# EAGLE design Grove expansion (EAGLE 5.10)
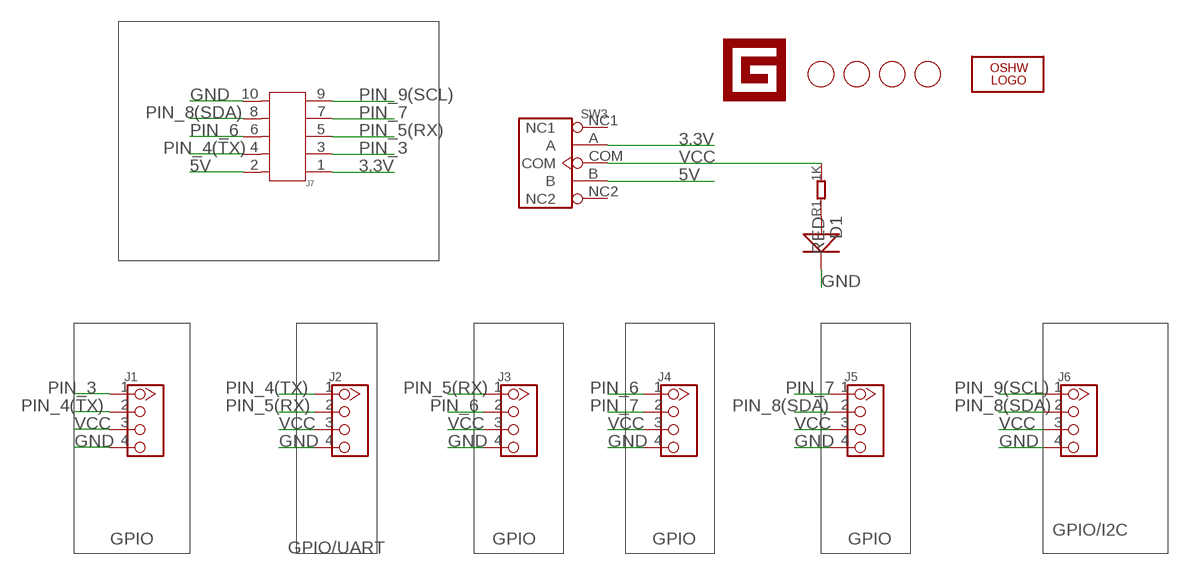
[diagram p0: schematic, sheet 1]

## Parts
D1  RED  D-0603  [SOD523]
J1  TWIG-4P-2.0-2.0  [4P-2.0]
J2  TWIG-4P-2.0-2.0  [4P-2.0]
J3  TWIG-4P-2.0-2.0  [4P-2.0]
J4  TWIG-4P-2.0-2.0  [4P-2.0]
J5  TWIG-4P-2.0-2.0  [4P-2.0]
J6  TWIG-4P-2.0-2.0  [4P-2.0]
J7  HEADER-SHF-105-01-L-D-SM  [SHF-105-01-L-D-SM]
LOGO2  LOGO-OSHW-FILLX0150-NT  [OSHW_FILLX150_NOTEXT]
R1  1K  R-0603  [0603]
SW3  SWITCH-2H-3P-REINFORCE  [3P-2CH-2.0-8.8X4.4X4.7H-90D-REINFORCE]
U$1  LOGO-GADGETEER-NORMAL  [GADGETEER-SILK]
U$2  PAD-HOLE'3.2/7.0'  [HOLE-D-3.2/7.0]
U$3  PAD-HOLE'3.2/7.0'  [HOLE-D-3.2/7.0]
U$4  PAD-HOLE'3.2/7.0'  [HOLE-D-3.2/7.0]
U$5  PAD-HOLE'3.2/7.0'  [HOLE-D-3.2/7.0]

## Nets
3.3V: J7.1 SW3.A
5V: J7.2 SW3.B
GND: D1.- J1.4 J2.4 J3.4 J4.4 J5.4 J6.4 J7.10
N$1: D1.+ R1.1
PIN_3: J1.1 J7.3
PIN_4(TX): J1.2 J2.1 J7.4
PIN_5(RX): J2.2 J3.1 J7.5
PIN_6: J3.2 J4.1 J7.6
PIN_7: J4.2 J5.1 J7.7
PIN_8(SDA): J5.2 J6.2 J7.8
PIN_9(SCL): J6.1 J7.9
VCC: J1.3 J2.3 J3.3 J4.3 J5.3 J6.3 R1.2 SW3.COM
Unconnected: SW3.NC1 SW3.NC2

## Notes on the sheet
- GPIO/I2C
- GPIO | GPIO | GPIO | GPIO
- GPIO/UART

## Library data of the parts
D1 = Discrete:D*
J1-J6 = Connector:TWIG-4P-2.0
J7 = Connector:HEADER-SHF-105-01-L-D-SM
LOGO2 = Logo:LOGO-OSHW-FILL
R1 = Discrete:R*
SW3 = Discrete:SWITCH-2H-3P-REINFORCE
U$1 = Logo:LOGO-GADGETEER
U$2-U$5 = Discrete:PAD-HOLE

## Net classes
0 default: width 0.152 mm, drill 0.305 mm, clearance 0.152 mm

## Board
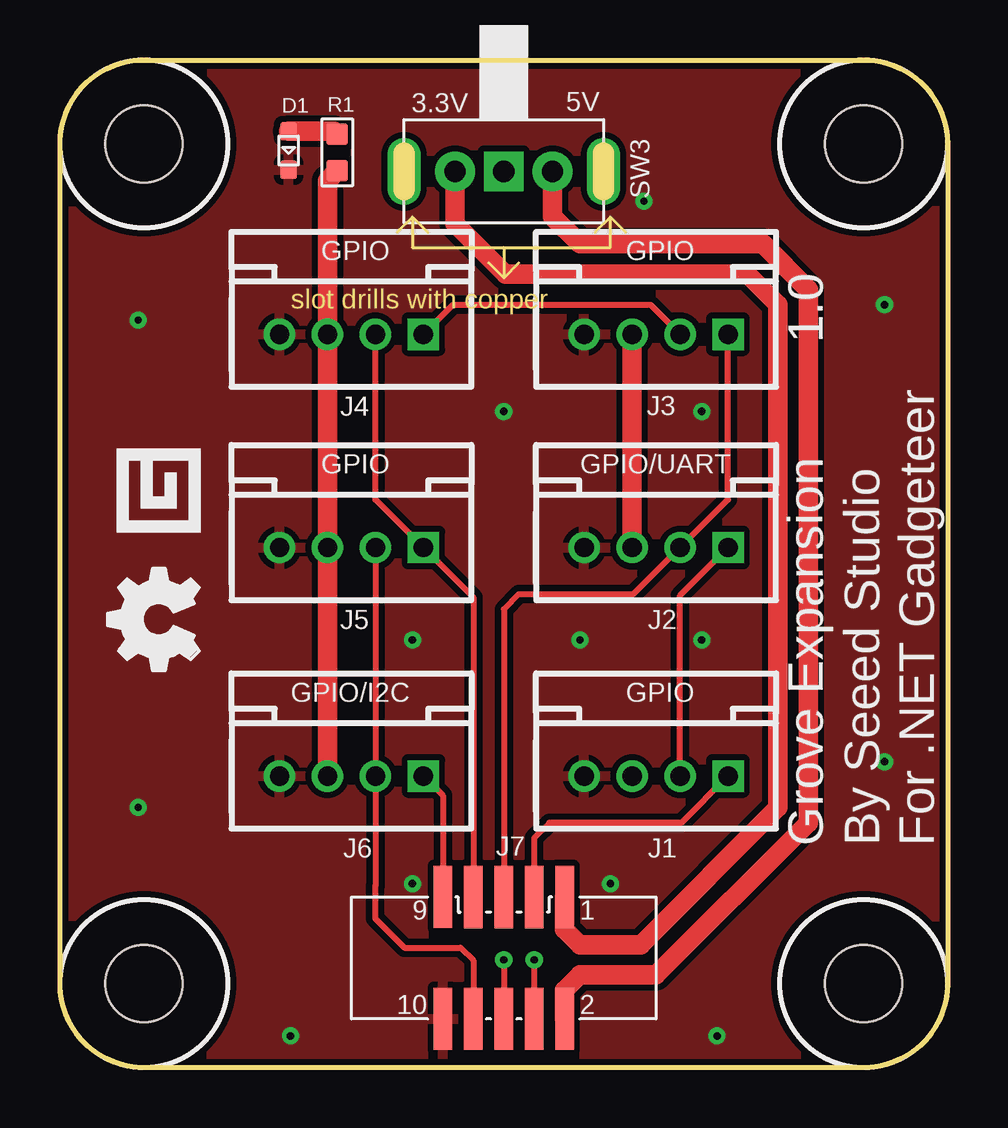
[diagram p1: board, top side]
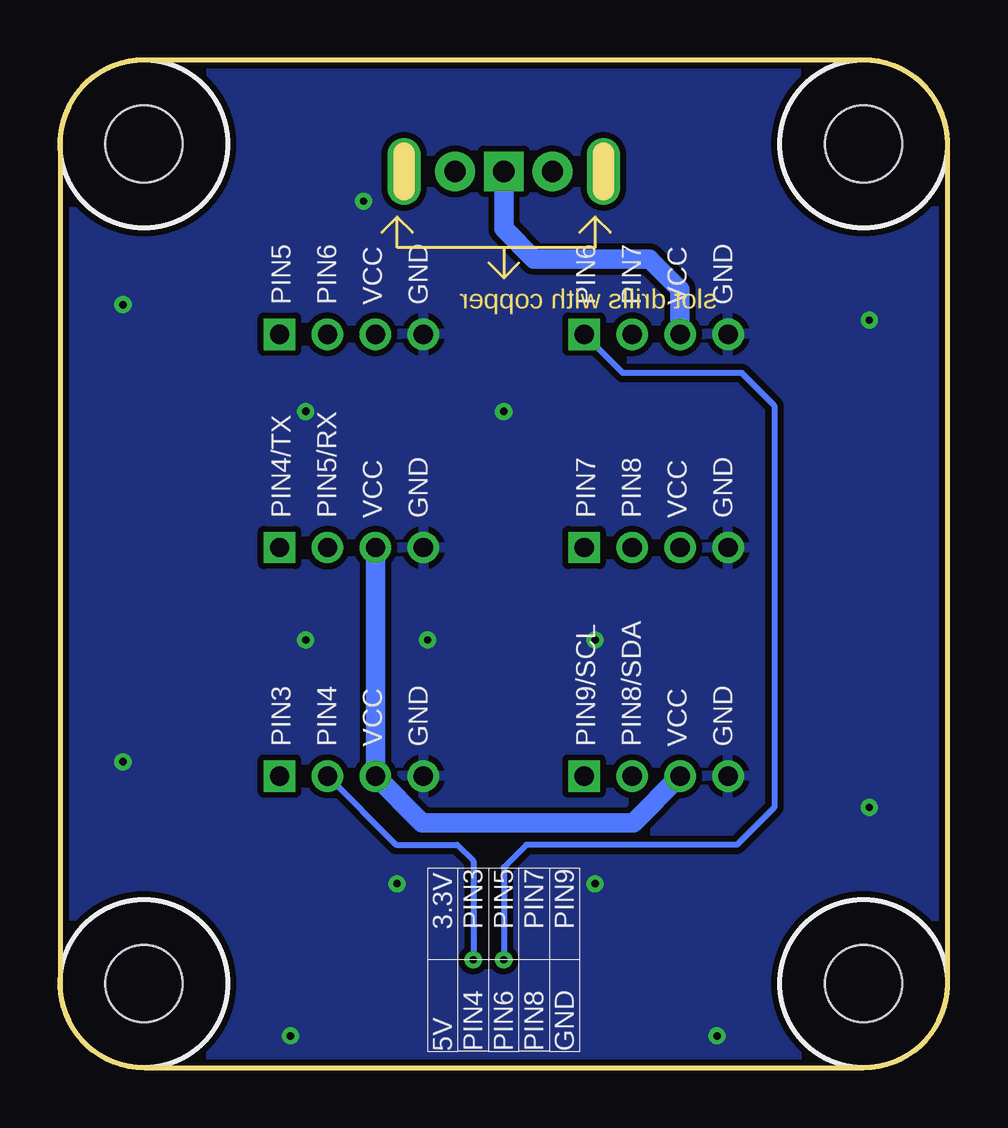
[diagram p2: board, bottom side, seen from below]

Size 37 x 42 mm. Coordinates in mm from the lower left corner, seen from the top.
Outline: 0,38.5 arc-90 3.5,42 33.5,42 arc-90 37,38.5 37,3.5 arc-90 33.5,0 3.5,0 arc-90 0,3.5 0,38.5
Copper layers (1*16): Top 0.035mm / dielectric 1.5mm / Bottom 0.035mm
Design rules "default *": minimum track width 10mil, minimum drill 12mil, track to track 8mil, track to pad 8mil, pad to pad 8mil, via to via 8mil, smd to smd 8mil, copper to edge 10mil, drill to drill 8mil, minimum pad ring 10mil, minimum via ring 8mil, stop-mask expansion 4mil, vias tented up to drill 100mil, thermal gap 10mil

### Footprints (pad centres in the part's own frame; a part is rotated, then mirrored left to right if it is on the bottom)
SOD523 = smd 0.762 x 0.7: + -0.8,0; - 0.8,0
4P-2.0 = drill 0.8 pad 1.27 square: 1 -3,0 | drill 0.8 pad 1.27 round: 2 -1,0; 3 1,0; 4 3,0
SHF-105-01-L-D-SM = smd 0.762 x 2.6: 1 -2.54,-2.54; 2 -2.54,2.54; 3 -1.27,-2.54; 4 -1.27,2.54; 5 0,-2.54; 6 0,2.54; 7 1.27,-2.54; 8 1.27,2.54; 9 2.54,-2.546; 10 2.54,2.54
0603 = smd 0.889 x 0.889: 1 -0.762,0; 2 0.762,0
3P-2CH-2.0-8.8X4.4X4.7H-90D-REINFORCE = drill 0.889 pad 1.651 round: A 0,2.032; B 0,-2.032 | drill 0.889 pad 1.651 square: COM 0,0 | drill 0.762 pad 1.397 long: NC1 0,4.166; NC2 0,-4.166
HOLE-D-3.2/7.0 = hole 3.2: 0,0

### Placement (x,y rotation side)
D1  9.53,38.23 270 top
J1  24.85,12.15 180 top
J2  24.85,21.68 180 top
J3  24.85,30.56 180 top
J4  12.15,30.56 180 top
J5  12.15,21.68 180 top
J6  12.15,12.15 180 top
J7  18.5,4.57 180 top
LOGO2  5.8,16.55 90 top
R1  11.55,38.14 270 top
SW3  18.5,37.36 90 top
U$1  3.68,24.47 90 top
U$2  3.5,38.5 0 top
U$3  33.5,3.5 0 top
U$4  3.5,3.5 0 top
U$5  33.5,38.5 0 top

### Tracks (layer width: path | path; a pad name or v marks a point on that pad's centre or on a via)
3.3V
  Top 0.813: J7.1 21.04,5.76 21.68,5.12 24.21,5.12 29.93,10.84 29.93,31.8 28.66,33.06 18.58,33.06 16.47,35.17 SW3.A
5V
  Top 0.813: J7.2 21.04,3.22 21.68,3.86 24.85,3.86 31.2,10.21 31.2,32.43 29.3,34.34 21.68,34.34 20.53,35.48 SW3.B
GND  (via drill 0.3 pad 0.64)
  other vias: 3.26,10.84 3.26,31.16 34.38,31.8 27.39,1.32 9.61,1.32 34.38,12.74 24.34,36.11 18.5,27.35 14.69,17.82 21.68,17.82 26.76,27.35 26.76,17.82 22.95,7.66 14.69,7.66
  pour Top (isolate 0.254): 0.72,51.48 3.89,51.48 3.89,49.58 0.72,49.58
  pour Top (isolate 0.254): -0.55,43.23 38.19,43.23 38.19,-0.59 -0.55,-0.59
  pour Bottom (isolate 0.254): -0.55,43.23 38.19,43.23 38.19,-0.59 -0.55,-0.59
N$1
  Top 0.813: D1.+ 11.44,39.02 R1.1
PIN_3
  Top 0.254: J7.3 19.77,9.57 20.41,10.21 25.91,10.21 J1.1
PIN_4(TX)  (via drill 0.3 pad 0.64)
  Top 0.254: J1.2 25.85,19.68 J2.1 | v19.77,4.49 J7.4
  Bottom 0.254: v19.77,4.49 19.77,8.61 20.46,9.29 22.99,9.29 J1.2
PIN_5(RX)
  Top 0.254: J7.5 18.5,19.09 19.14,19.73 23.91,19.73 J2.2 27.85,23.68 J3.1
PIN_6  (via drill 0.3 pad 0.64)
  Top 0.254: J4.1 16.38,31.8 24.62,31.8 J3.2 | v18.5,4.49 J7.6
  Bottom 0.254: v18.5,4.49 18.5,8.35 17.56,9.29 8.77,9.29 7.22,10.84 7.22,27.6 8.57,28.95 13.54,28.95 J4.1
PIN_7
  Top 0.254: J7.7 17.23,19.59 J5.1 13.15,23.68 J4.2
PIN_8(SDA)
  Top 0.254: J5.2 J6.2 13.15,7.58 13.14,7.57 13.14,6.22 14.36,5 16.7,5 17.23,4.46 J7.8
PIN_9(SCL)
  Top 0.254: J7.9 15.96,11.34 J6.1
VCC
  Top 0.813: J2.3 J3.3 | R1.2 11.15,36.98 J4.3 J5.3 J6.3
  Bottom 0.813: J2.3 J1.3 21.91,10.21 13.09,10.21 J6.3 | J4.3 11.15,32.43 12.42,33.7 17.23,33.7 18.5,34.97 SW3.COM

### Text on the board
tPlace: 3.3V | 5V | GPIO | GPIO | 1.0 | GPIO | GPIO/UART | GPIO/I2C | GPIO | Grove Expansion | By Seeed Studio | For .NET Gadgeteer
bPlace: GND | VCC | PIN7 | PIN6 | GND | VCC | PIN6 | PIN5 | GND | VCC | PIN8 | PIN7 | GND | VCC | PIN5/RX | PIN4/TX | GND | VCC | PIN8/SDA | PIN9/SCL | GND | VCC | PIN4 | PIN3 | PIN9 | PIN7 | PIN5 | PIN3 | 3.3V | GND | PIN8 | PIN6 | PIN4 | 5V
